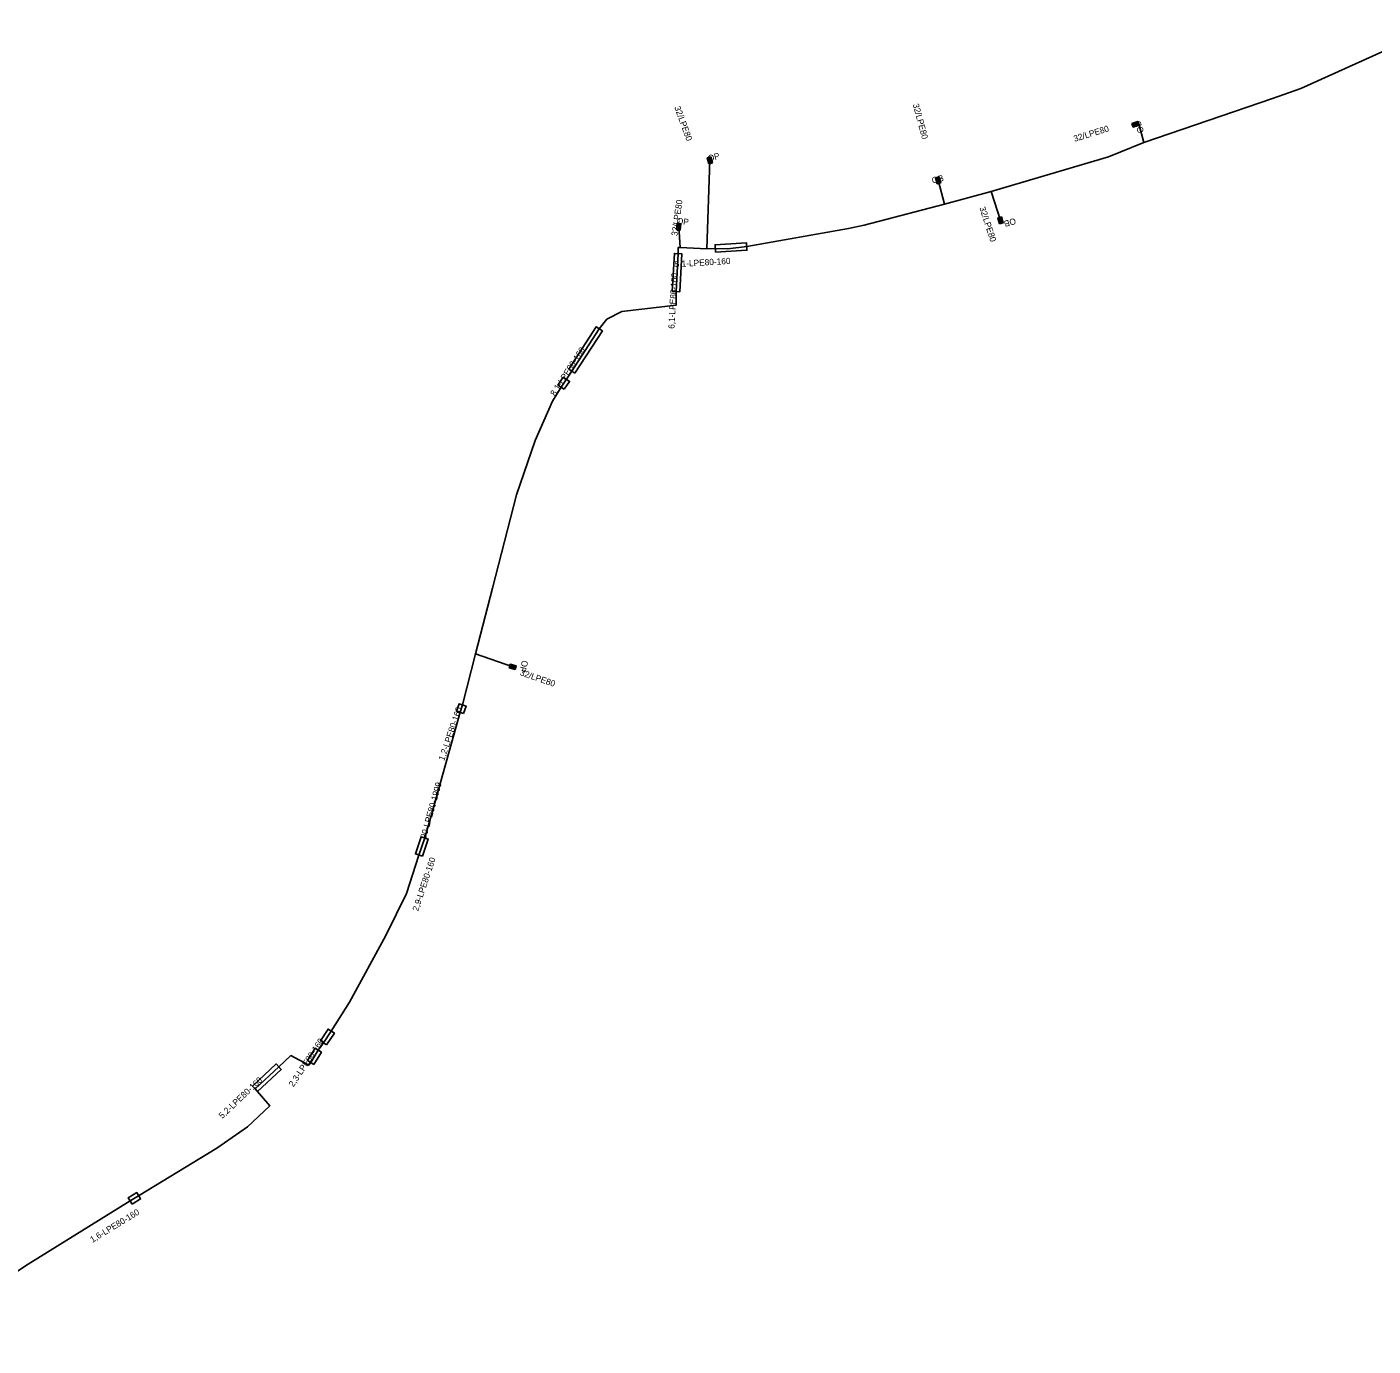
# Model space of a CAD drawing. Extents: x -762509 to -761250, y -1153000 to -1152256.
# Drawn here: x -761877.8 to -761661, y -1152684.9 to -1152472.4 of the extents above; entities that cross this region are included whole.
import ezdxf

# ---------------------------------------------------------------- set-up
doc = ezdxf.new("R2010")
doc.units = 0
for name, color, linetype in [('Vrstva 21', 7, 'Continuous'), ('Vrstva 29', 7, 'Continuous'), ('Vrstva 31', 7, 'Continuous'), ('Vrstva 32', 7, 'Continuous')]:
    doc.layers.add(name, color=color, linetype=linetype)

msp = doc.modelspace()

# ---------------------------------------------------------------- linework, layer by layer
at = {"layer": 'Vrstva 21'}
msp.add_lwpolyline([(-761897.51, -1152684.88), (-761877.63, -1152671.71), (-761861.19, -1152661.5), (-761859.83, -1152660.67), (-761847.23, -1152653), (-761842.28, -1152649.55), (-761838.7, -1152646.19), (-761841.07, -1152643.46), (-761837.27, -1152639.89), (-761835.31, -1152638.09), (-761832.43, -1152639.66), (-761832.12, -1152639.22), (-761830.9, -1152637.22), (-761830.06, -1152636.03), (-761828.81, -1152634.15), (-761825.86, -1152629.52), (-761820.03, -1152618.78), (-761816.71, -1152611.99), (-761814.68, -1152605.81), (-761813.76, -1152603.04), (-761812.61, -1152599.09), (-761808.06, -1152582.82), (-761807.66, -1152581.64), (-761805.56, -1152573.43), (-761802.83, -1152562.81), (-761798.99, -1152547.82), (-761795.95, -1152539.03), (-761793.16, -1152532.74), (-761791.8, -1152530.46), (-761790.94, -1152529.2), (-761790.06, -1152527.88), (-761785.64, -1152521.07), (-761784.41, -1152519.51), (-761782, -1152518.29), (-761773.29, -1152517.28), (-761773.29, -1152515.06), (-761772.96, -1152508.95), (-761772.97, -1152507.99), (-761772.61, -1152507.96), (-761768.31, -1152508.21), (-761766.95, -1152508.12), (-761764.97, -1152508.17), (-761761.9, -1152507.82), (-761745.5, -1152504.91), (-761743, -1152504.4), (-761730.03, -1152500.99), (-761722.56, -1152498.96), (-761703.63, -1152493.35), (-761697.97, -1152491.04), (-761677.24, -1152483.96), (-761672.69, -1152482.38), (-761650.69, -1152472.45)], dxfattribs=at)
at = {"layer": 'Vrstva 29'}
for points in [[(-761772.69, -1152515.09), (-761772.36, -1152508.98), (-761773.56, -1152508.92), (-761773.89, -1152515.03)], [(-761766.91, -1152508.72), (-761761.86, -1152508.42), (-761761.94, -1152507.22), (-761766.99, -1152507.52)], [(-761789.56, -1152528.21), (-761785.14, -1152521.4), (-761786.14, -1152520.74), (-761790.56, -1152527.55)], [(-761791.3, -1152530.8), (-761790.44, -1152529.54), (-761791.44, -1152528.86), (-761792.3, -1152530.12)], [(-761807.49, -1152583.01), (-761807.09, -1152581.83), (-761808.23, -1152581.45), (-761808.63, -1152582.63)], [(-761814.11, -1152606), (-761813.19, -1152603.23), (-761814.33, -1152602.85), (-761815.25, -1152605.62)], [(-761829.56, -1152636.36), (-761828.31, -1152634.48), (-761829.31, -1152633.82), (-761830.56, -1152635.7)], [(-761831.61, -1152639.53), (-761830.39, -1152637.53), (-761831.41, -1152636.91), (-761832.63, -1152638.91)], [(-761840.66, -1152643.9), (-761836.86, -1152640.33), (-761837.68, -1152639.45), (-761841.48, -1152643.02)], [(-761860.88, -1152662.01), (-761859.52, -1152661.18), (-761860.14, -1152660.16), (-761861.5, -1152660.99)]]:
    msp.add_lwpolyline(points, close=True, dxfattribs=at)
at = {"layer": 'Vrstva 31'}
for points in [[(-761697.97, -1152491.04), (-761698.75, -1152488.05), (-761699.3, -1152488.13)], [(-761768.31, -1152508.21), (-761767.84, -1152493.93)], [(-761730.03, -1152500.99), (-761731.07, -1152497.15)], [(-761722.56, -1152498.96), (-761721.04, -1152503.62)], [(-761772.61, -1152507.96), (-761772.86, -1152504.6)], [(-761805.56, -1152573.43), (-761799.58, -1152575.5)]]:
    msp.add_lwpolyline(points, dxfattribs=at)
at = {"layer": 'Vrstva 32'}
for p, q in [((-761699.736, -1152488.106), (-761699.613, -1152488.434)), ((-761699.678, -1152488.26), (-761699.49, -1152488.19)), ((-761699.425, -1152488.363), (-761699.547, -1152488.036)), ((-761699.051, -1152488.224), (-761699.173, -1152487.896)), ((-761767.773, -1152493.499), (-761768.111, -1152493.588)), ((-761768.06, -1152493.783), (-761767.722, -1152493.693)), ((-761767.932, -1152493.541), (-761767.881, -1152493.735)), ((-761767.959, -1152494.168), (-761767.62, -1152494.079)), ((-761731.006, -1152496.718), (-761731.343, -1152496.809)), ((-761731.291, -1152497.003), (-761730.953, -1152496.912)), ((-761731.187, -1152497.388), (-761730.849, -1152497.297)), ((-761731.165, -1152496.761), (-761731.112, -1152496.955)), ((-761773.057, -1152504.778), (-761772.71, -1152504.819)), ((-761773.011, -1152504.382), (-761772.663, -1152504.423)), ((-761772.64, -1152504.223), (-761772.987, -1152504.182)), ((-761772.803, -1152504.204), (-761772.827, -1152504.403)), ((-761720.928, -1152503.378), (-761721.264, -1152503.477)), ((-761720.816, -1152503.761), (-761721.152, -1152503.86)), ((-761721.095, -1152504.053), (-761720.759, -1152503.954)), ((-761720.937, -1152504.006), (-761720.993, -1152503.813)), ((-761799.729, -1152575.28), (-761799.817, -1152575.619)), ((-761799.343, -1152575.381), (-761799.431, -1152575.719)), ((-761799.195, -1152575.61), (-761799.389, -1152575.56)), ((-761799.236, -1152575.77), (-761799.148, -1152575.431))]:
    msp.add_line(p, q, dxfattribs=at)
for points in [[(-761699.873, -1152488.024), (-761698.936, -1152487.674), (-761698.726, -1152488.236), (-761699.663, -1152488.586), (-761699.873, -1152488.024)], [(-761699.455, -1152488.001), (-761699.367, -1152488.236), (-761699.337, -1152488.277), (-761699.296, -1152488.297), (-761699.251, -1152488.298), (-761699.224, -1152488.288), (-761699.19, -1152488.258), (-761699.175, -1152488.217), (-761699.179, -1152488.166), (-761699.266, -1152487.931)], [(-761699.173, -1152487.896), (-761699.052, -1152487.851), (-761699.006, -1152487.852), (-761698.987, -1152487.862), (-761698.962, -1152487.888), (-761698.945, -1152487.935), (-761698.946, -1152487.97), (-761698.955, -1152487.991), (-761698.988, -1152488.021), (-761699.11, -1152488.067)], [(-761767.677, -1152493.371), (-761767.423, -1152494.338), (-761768.003, -1152494.49), (-761768.258, -1152493.523), (-761767.677, -1152493.371)], [(-761767.696, -1152493.789), (-761767.939, -1152493.853), (-761767.983, -1152493.879), (-761768.007, -1152493.918), (-761768.013, -1152493.962), (-761768.005, -1152493.991), (-761767.978, -1152494.027), (-761767.939, -1152494.046), (-761767.888, -1152494.047), (-761767.645, -1152493.984)], [(-761767.62, -1152494.079), (-761767.587, -1152494.205), (-761767.593, -1152494.25), (-761767.604, -1152494.269), (-761767.633, -1152494.29), (-761767.681, -1152494.303), (-761767.717, -1152494.298), (-761767.736, -1152494.288), (-761767.763, -1152494.251), (-761767.796, -1152494.126)], [(-761730.911, -1152496.588), (-761730.65, -1152497.554), (-761731.229, -1152497.711), (-761731.49, -1152496.745), (-761730.911, -1152496.588)], [(-761730.927, -1152497.007), (-761731.169, -1152497.073), (-761731.213, -1152497.099), (-761731.237, -1152497.138), (-761731.242, -1152497.183), (-761731.235, -1152497.211), (-761731.207, -1152497.247), (-761731.168, -1152497.266), (-761731.117, -1152497.267), (-761730.875, -1152497.201)], [(-761730.849, -1152497.297), (-761730.815, -1152497.422), (-761730.82, -1152497.467), (-761730.832, -1152497.486), (-761730.86, -1152497.508), (-761730.908, -1152497.521), (-761730.944, -1152497.516), (-761730.963, -1152497.506), (-761730.99, -1152497.47), (-761731.024, -1152497.344)], [(-761772.504, -1152504.139), (-761772.621, -1152505.132), (-761773.217, -1152505.061), (-761773.1, -1152504.068), (-761772.504, -1152504.139)], [(-761772.675, -1152504.521), (-761772.924, -1152504.492), (-761772.974, -1152504.5), (-761773.011, -1152504.527), (-761773.032, -1152504.567), (-761773.036, -1152504.595), (-761773.024, -1152504.639), (-761772.994, -1152504.672), (-761772.947, -1152504.691), (-761772.698, -1152504.721)], [(-761772.71, -1152504.819), (-761772.725, -1152504.948), (-761772.747, -1152504.988), (-761772.764, -1152505.001), (-761772.799, -1152505.011), (-761772.848, -1152505.005), (-761772.88, -1152504.987), (-761772.894, -1152504.971), (-761772.906, -1152504.927), (-761772.891, -1152504.798)], [(-761721.187, -1152504.184), (-761721.469, -1152503.225), (-761720.893, -1152503.055), (-761720.611, -1152504.015), (-761721.187, -1152504.184)], [(-761721.264, -1152503.477), (-761721.301, -1152503.352), (-761721.296, -1152503.307), (-761721.285, -1152503.288), (-761721.258, -1152503.266), (-761721.21, -1152503.252), (-761721.174, -1152503.256), (-761721.154, -1152503.266), (-761721.126, -1152503.301), (-761721.09, -1152503.426)], [(-761721.18, -1152503.765), (-761720.939, -1152503.694), (-761720.896, -1152503.667), (-761720.873, -1152503.628), (-761720.868, -1152503.583), (-761720.877, -1152503.555), (-761720.905, -1152503.519), (-761720.945, -1152503.501), (-761720.996, -1152503.501), (-761721.236, -1152503.572)], [(-761799.171, -1152575.916), (-761800.139, -1152575.665), (-761799.988, -1152575.084), (-761799.02, -1152575.335), (-761799.171, -1152575.916)], [(-761799.817, -1152575.619), (-761799.943, -1152575.587), (-761799.979, -1152575.56), (-761799.99, -1152575.54), (-761799.995, -1152575.505), (-761799.983, -1152575.457), (-761799.961, -1152575.428), (-761799.942, -1152575.416), (-761799.897, -1152575.41), (-761799.771, -1152575.443)], [(-761799.527, -1152575.695), (-761799.464, -1152575.452), (-761799.465, -1152575.401), (-761799.487, -1152575.361), (-761799.523, -1152575.334), (-761799.551, -1152575.327), (-761799.596, -1152575.333), (-761799.632, -1152575.357), (-761799.658, -1152575.401), (-761799.721, -1152575.644)]]:
    msp.add_lwpolyline(points, dxfattribs=at)

# ---------------------------------------------------------------- texts
at = {"layer": 'Vrstva 21'}
msp.add_text('90-LPE80-1999', height=1, rotation=74.3618, dxfattribs=at).set_placement((-761813.53, -1152603.26))
at = {"layer": 'Vrstva 29'}
for s, rotation, p in [('5,1-LPE80-160', 3.39971, (-761773.47, -1152511.15)), ('6,1-LPE80-160', 86.90847, (-761773.54, -1152521.08)), ('8,1-LPE80-160', 57.01459, (-761792.78, -1152531.98)), ('1,2-LPE80-160', 71.27421, (-761810.62, -1152590.69)), ('2,9-LPE80-160', 71.62713, (-761814.82, -1152614.92)), ('2,3-LPE80-160', 56.38032, (-761834.91, -1152643.23)), ('5,2-LPE80-160', 43.21252, (-761846.36, -1152648.33)), ('1,6-LPE80-160', 31.39547, (-761867.26, -1152668.27))]:
    msp.add_text(s, height=1, rotation=rotation, dxfattribs=at).set_placement(p)
at = {"layer": 'Vrstva 31'}
for rotation, p in [(290.05185, (-761773.58, -1152485.4)), (290.05185, (-761773.58, -1152485.4)), (285.15407, (-761735.18, -1152484.94)), (285.15407, (-761735.18, -1152484.94)), (17.0688, (-761709.1, -1152490.96)), (17.0688, (-761709.1, -1152490.96)), (81.82364, (-761773.07, -1152506.17)), (81.82364, (-761773.07, -1152506.17)), (288.0653, (-761724.45, -1152501.58)), (288.0653, (-761724.45, -1152501.58)), (340.90651, (-761798.5, -1152576.82)), (340.90651, (-761798.5, -1152576.82))]:
    msp.add_text('32/LPE80', height=1, rotation=rotation, dxfattribs=at).set_placement(p)
at = {"layer": 'Vrstva 32'}
for s, rotation, p in [('OB', 110.44423, (-761697.9, -1152489.32)), ('OB', 110.44423, (-761697.9, -1152489.32)), ('OP', 14.75456, (-761768.03, -1152494.15)), ('OP', 14.75456, (-761768.03, -1152494.15)), ('OB', 15.15407, (-761731.95, -1152497.71)), ('OB', 15.15407, (-761731.95, -1152497.71)), ('OP', 353.27875, (-761773.21, -1152504.15)), ('OP', 353.27875, (-761773.21, -1152504.15)), ('OB', 196.37367, (-761718.73, -1152503.19)), ('OB', 196.37367, (-761718.73, -1152503.19)), ('OP', 255.47146, (-761798.04, -1152574.37)), ('OP', 255.47146, (-761798.04, -1152574.37))]:
    msp.add_text(s, height=1, rotation=rotation, dxfattribs=at).set_placement(p)

doc.saveas('drawing.dxf')
